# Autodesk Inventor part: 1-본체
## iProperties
Created: 2015-06
Part Number: 1-본체
Document SubType Name: Modeling
Designer: elite
Density: 2.71 g/cm^3
Material: 알루미늄-6061
Mass: 3275.6 g
Surface Area: 2299.07 cm^2
Volume: 1208.71 cm^3
Author: elite
